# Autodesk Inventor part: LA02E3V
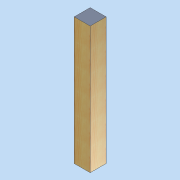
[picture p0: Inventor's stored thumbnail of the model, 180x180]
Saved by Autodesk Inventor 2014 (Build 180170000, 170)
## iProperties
Created: 2011-04
Part Number: LA02E3V
Document SubType Name: Modeling
Designer: david.appleford
Density: 0.44 g/cm^3
Description: Lug End 0.5w 3 Slots
Mass: 1102.73 g
Surface Area: 1566.72 cm^2
Volume: 2506.21 cm^3
Cost Center: £6.00
Material: 000 Redwood
Appearance: Wood (Pine)
Justset: False
Author: david.appleford
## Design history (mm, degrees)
sketch "Sketch1"
  geometry: L1 (0, 0)-(68, 0); L2 (68, 0)-(68, 68); L3 (68, 68)-(0, 68); L4 (0, 68)-(0, 0)
  constraints: 8 end point, 2 parallel, 1 horizontal, 1 perpendicular
  dimensions: "d0" = 68 distance between parallel lines of L2 L4 (= t); "d1" = 68 distance between parallel lines of L1 L3 (= t)
extrude "Extrusion1" new body sketch "Sketch1" distance "d2" = 542; taper "d3" = 0 deg
body "Solid1"
other parameters: "t" = 68 [user parameter; used in 2 equation terms], "Cl" = 2 [user parameter]
